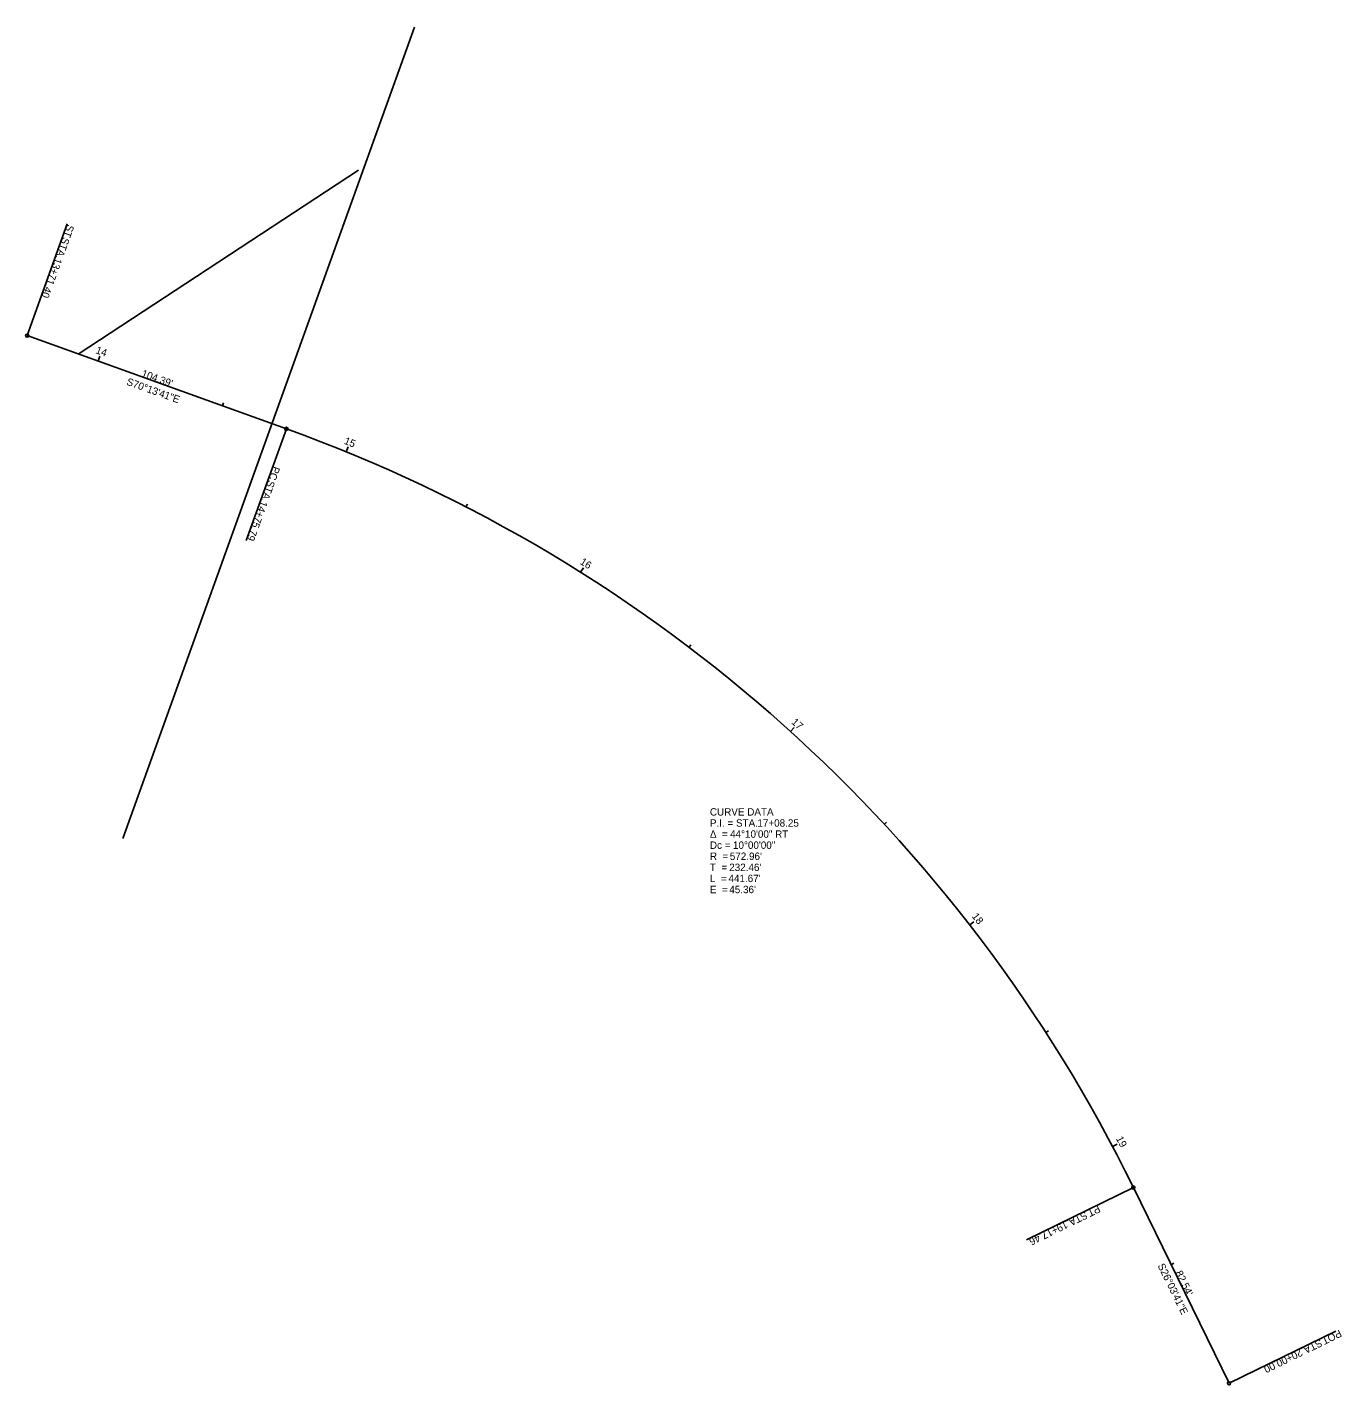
# Model space of a CAD drawing. Extents: x 2331955 to 2333190, y 280152 to 281038.
# Drawn here: x 2332692 to 2333190, y 280152 to 280667 of the extents above; entities that cross this region are included whole.
import ezdxf

# ---------------------------------------------------------------- set-up
doc = ezdxf.new("R2010")
doc.units = 0
for name, color, linetype in [('_CIVIL_CONSTRUCTION', 7, 'Continuous'), ('Default', 7, 'Continuous'), ('PF_X_Ground_Line', 7, 'Continuous'), ('RW_X_Esmt_SH', 7, 'Continuous'), ('RW_X_Esmt_SL', 7, 'Continuous'), ('RW_X_Fee_RW', 7, 'Continuous'), ('SC_Scratch1', 7, 'Continuous'), ('SV_X_Text', 7, 'Continuous')]:
    doc.layers.add(name, color=color, linetype=linetype)

msp = doc.modelspace()

# ---------------------------------------------------------------- linework, layer by layer
at = {"layer": '_CIVIL_CONSTRUCTION'}
for p, q in [((2332691.76, 280549.95), (2332790, 280514.64)), ((2333110.88, 280227.18), (2333147.14, 280153.03))]:
    msp.add_line(p, q, dxfattribs=at)
msp.add_arc((2332596.18, 279975.46), 572.96, 26.0613, 70.228, dxfattribs=at)
at = {"layer": 'Default'}
for p, q in [((2332728.06, 280359.47), (2332838.55, 280666.83)), ((2332691.76, 280549.95), (2332790, 280514.64)), ((2333110.88, 280227.18), (2333147.14, 280153.03))]:
    msp.add_line(p, q, dxfattribs=at)
msp.add_arc((2332596.18, 279975.46), 572.96, 26.0613, 70.228, dxfattribs=at)
at = {"layer": 'RW_X_Fee_RW'}
for p, q in [((2332691.76, 280549.95), (2332706.98, 280592.3)), ((2332790, 280514.64), (2332774.77, 280472.29)), ((2333110.88, 280227.18), (2333070.45, 280207.41)), ((2333147.14, 280153.03), (2333187.57, 280172.8))]:
    msp.add_line(p, q, dxfattribs=at)
for centre in [(2332691.76, 280549.95), (2332790, 280514.64), (2333110.88, 280227.18), (2333147.14, 280153.03)]:
    msp.add_circle(centre, 0.6, dxfattribs=at)
at = {"layer": 'SC_Scratch1'}
msp.add_line((2332817.33, 280612.66), (2332711.15, 280542.98), dxfattribs=at)
at = {"layer": 'SV_X_Text'}
for p, q in [((2332718.67, 280540.27), (2332719.35, 280542.16)), ((2332765.73, 280523.36), (2332766.13, 280524.49)), ((2332812.6, 280505.97), (2332813.35, 280507.82)), ((2332858.01, 280485.09), (2332858.56, 280486.15)), ((2332901.43, 280460.33), (2332902.5, 280462.02)), ((2332942.53, 280431.88), (2332943.26, 280432.83)), ((2332980.99, 280399.95), (2332982.34, 280401.44)), ((2333016.53, 280364.8), (2333017.41, 280365.61)), ((2333048.86, 280326.68), (2333050.44, 280327.91)), ((2333077.75, 280285.89), (2333078.76, 280286.54)), ((2333102.97, 280242.74), (2333104.74, 280243.67)), ((2333125.18, 280197.94), (2333126.25, 280198.47))]:
    msp.add_line(p, q, dxfattribs=at)

# ---------------------------------------------------------------- texts
at = {"layer": 'PF_X_Ground_Line'}
for s, rotation, p in [("104.39'", 340.228, (2332734.83, 280534.51)), ("82.54'", 296.0613, (2333126.71, 280194.9))]:
    msp.add_text(s, height=2.8, rotation=rotation, dxfattribs=at).set_placement(p)
at = {"layer": 'RW_X_Esmt_SH'}
for s, p in [('CURVE DATA', (2332950.44, 280368.11)), ('Δ  = ', (2332950.44, 280359.71)), ('P.I. = STA. ', (2332950.44, 280363.91)), ('44°10\'00" RT', (2332958.08, 280359.71)), ('17+08.25', (2332968.43, 280363.91)), ('Dc = ', (2332950.44, 280355.51)), ('10°00\'00"', (2332959.18, 280355.51)), ('R  = ', (2332950.44, 280351.31)), ("572.96'", (2332957.97, 280351.31)), ('T  = ', (2332950.44, 280347.11)), ("232.46'", (2332957.76, 280347.11)), ('L  = ', (2332950.44, 280342.91)), ('E  = ', (2332950.44, 280338.71)), ("441.67'", (2332957.47, 280342.91)), ("45.36'", (2332957.78, 280338.71))]:
    msp.add_text(s, height=2.8, dxfattribs=at).set_placement(p)
at = {"layer": 'RW_X_Esmt_SL'}
for s, rotation, p in [('S70°13\'41"E', 340.228, (2332729.18, 280531.4)), ('S26°03\'41"E', 296.0613, (2333119.99, 280197.61))]:
    msp.add_text(s, height=2.8, rotation=rotation, dxfattribs=at).set_placement(p)
at = {"layer": 'RW_X_Fee_RW'}
for s, rotation, p in [('ST', 250.228, (2332707.01, 280592.26)), (' STA. ', 250.228, (2332705.62, 280588.39)), ('13+71.40', 250.228, (2332702.46, 280579.62)), ('PC', 250.228, (2332785.02, 280500.68)), (' STA. ', 250.228, (2332783.46, 280496.35)), ('14+75.79', 250.228, (2332780.31, 280487.57)), (' STA. ', 206.0613, (2333093.58, 280218.68)), ('PT', 206.0613, (2333097.49, 280220.59)), ('19+17.46', 206.0613, (2333085.21, 280214.58)), ('POT', 206.0613, (2333188.92, 280173.42)), (' STA. ', 206.0613, (2333182.51, 280170.28)), ('20+00.00', 206.0613, (2333174.14, 280166.19))]:
    msp.add_text(s, height=2.8, rotation=rotation, dxfattribs=at).set_placement(p)
at = {"layer": 'SV_X_Text'}
for s, rotation, p in [('14', 340.228, (2332717.48, 280543.36)), ('15', 337.807, (2332811.61, 280509.07)), ('16', 327.807, (2332900.96, 280463.58)), ('17', 317.807, (2332981.1, 280403.23)), ('18', 307.807, (2333049.53, 280329.9)), ('19', 297.807, (2333104.2, 280245.77))]:
    msp.add_text(s, height=2.8, rotation=rotation, dxfattribs=at).set_placement(p)

doc.saveas('drawing.dxf')
